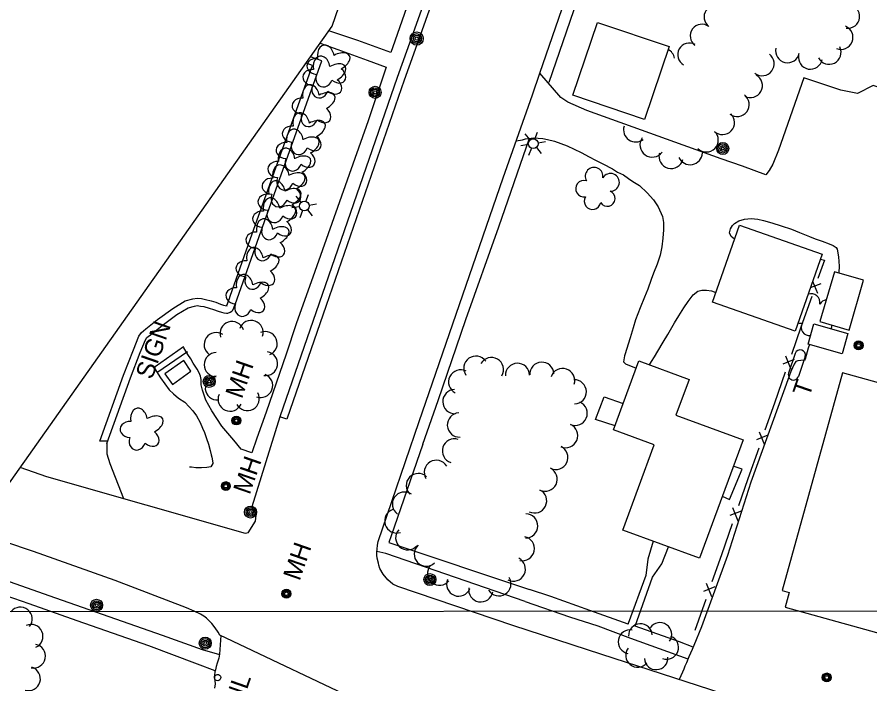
# Model space of a CAD drawing. Extents: x 189384 to 193282, y 256970 to 260388.
# Drawn here: x 190295.2 to 190581.3, y 258486.9 to 258710.5 of the extents above; entities that cross this region are included whole.
import ezdxf

# ---------------------------------------------------------------- set-up
doc = ezdxf.new("R2010")
doc.units = 0
for name, color, linetype in [('E_BLD', 7, 'Continuous'), ('E_BLD_Name', 7, 'Continuous'), ('E_DRN_Grate', 7, 'Continuous'), ('E_DWY', 7, 'Continuous'), ('E_LAND_Vegetation', 7, 'Continuous'), ('E_MAP_GridLines', 7, 'Continuous'), ('E_MAP_Limits', 7, 'Continuous'), ('E_MISCPROP', 7, 'Continuous'), ('E_MISCPROP_HvyDash', 7, 'Continuous'), ('E_MISCPROP_HvyLine', 7, 'Continuous'), ('E_MISCPROP_Railing', 7, 'Continuous'), ('E_PATH_Sidewalk', 7, 'Continuous'), ('E_RDWY', 7, 'Continuous')]:
    doc.layers.add(name, color=color, linetype=linetype)

# ---------------------------------------------------------------- blocks, each defined once
blk = doc.blocks.new('INL')
at = {"layer": 'E_MISCPROP_Railing'}
blk.add_text('INL', height=6, rotation=0, dxfattribs=at).set_placement((-5.79, -2.75))
blk = doc.blocks.new('MHO')
at = {"layer": 'E_DRN_Grate'}
for centre, radius in [((0.04, -0.06), 1.5), ((0.04, -0.06), 1.22), ((0.04, -0.07), 0.968), ((0.01, -0.08), 0.605)]:
    blk.add_circle(centre, radius, dxfattribs=at)
blk = doc.blocks.new('SIGN')
at = {"layer": 'E_MISCPROP'}
blk.add_text('SIGN', height=6, rotation=0, dxfattribs=at).set_placement((0, -3))
blk = doc.blocks.new('LTP')
at = {"layer": 'E_MISCPROP'}
for p, q in [((-0.78, 1.46), (-1.98, 3.76)), ((0.86, 1.37), (2.22, 3.6)), ((-1.61, 0.09), (-4.22, 0.17)), ((1.66, 0), (4.18, -0.06)), ((-0.86, -1.4), (-2.22, -3.59)), ((0.78, -1.44), (2.02, -3.62))]:
    blk.add_line(p, q, dxfattribs=at)
blk.add_circle((0.02, 0.01), 1.64, dxfattribs=at)
blk = doc.blocks.new('POLE')
at = {"layer": 'E_MISCPROP'}
for radius in [2.02, 1.51, 1.01, 0.504]:
    blk.add_circle((0.03, -0.09), radius, dxfattribs=at)
blk = doc.blocks.new('MHO_2')
at = {"layer": 'E_DRN_Grate'}
for centre, radius in [((0.04, -0.06), 1.5), ((0.04, -0.06), 1.22), ((0.04, -0.07), 0.968), ((0.01, -0.08), 0.605)]:
    blk.add_circle(centre, radius, dxfattribs=at)
blk = doc.blocks.new('TREE')
at = {"layer": 'E_LAND_Vegetation'}
for centre, major_axis, ratio in [((-1.07, 3.38), (0.91, -3.32), 0.782863), ((2.88, 1.66), (-3.52, -1.95), 0.691916), ((-3.74, -0.07), (3.29, -0.08), 0.832022), ((-1.48, -3.66), (1.2, 3.24), 0.716896), ((2.54, -2.64), (-3.34, 3.06), 0.560249)]:
    blk.add_ellipse(centre, major_axis=major_axis, ratio=ratio, start_param=1.570796, end_param=4.712389, dxfattribs=at)
blk = doc.blocks.new('MHO_4')
at = {"layer": 'E_DRN_Grate'}
for centre, radius in [((0.04, -0.06), 1.5), ((0.04, -0.06), 1.22), ((0.04, -0.07), 0.968), ((0.01, -0.08), 0.605)]:
    blk.add_circle(centre, radius, dxfattribs=at)
blk = doc.blocks.new('TK5')
at = {"layer": 'E_BLD'}
for p, q in [((1.56, 1.71), (8.66, 1.72)), ((1.66, -1.78), (8.68, -1.78))]:
    blk.add_line(p, q, dxfattribs=at)
for centre, start, end in [((1.67, -0.03), 93.5947, 269.612), ((8.66, -0.03), 270.7756, 93.236)]:
    blk.add_arc(centre, 1.75, start, end, dxfattribs=at)
blk = doc.blocks.new('TA')
at = {"layer": 'E_BLD_Name'}
blk.add_text('T', height=6, rotation=0, dxfattribs=at).set_placement((-1.9, 0.03))
blk = doc.blocks.new('TREE_1')
at = {"layer": 'E_LAND_Vegetation'}
for centre, radius, start, end in [((-1.47, 4.28), 2.78, 1.3946, 209.1676), ((-4.47, 0.2), 2.78, 78.0717, 279.0827), ((3.57, 2.42), 2.97, 278.4237, 139.6576), ((-2.01, -4.2), 2.61, 140.7798, 358.7124), ((3.46, -3.43), 2.97, 196.0746, 79.0478)]:
    blk.add_arc(centre, radius, start, end, dxfattribs=at)
blk = doc.blocks.new('LTP_2')
at = {"layer": 'E_MISCPROP'}
for p, q in [((-0.8, 1.43), (-2, 3.73)), ((0.9, 1.42), (2.27, 3.65)), ((-1.63, 0.07), (-4.24, 0.14)), ((-0.88, -1.42), (-2.24, -3.61)), ((0.76, -1.47), (2, -3.65)), ((1.64, -0.02), (4.16, -0.09))]:
    blk.add_line(p, q, dxfattribs=at)
blk.add_circle((0, 0), 1.64, dxfattribs=at)
blk = doc.blocks.new('POLE_10')
at = {"layer": 'E_MISCPROP'}
for centre, radius in [((-0.01, 0.02), 2.02), ((-0.01, 0.03), 1.52), ((0, -0.01), 1.01), ((0, 0), 0.502)]:
    blk.add_circle(centre, radius, dxfattribs=at)
blk = doc.blocks.new('POLE_12')
at = {"layer": 'E_MISCPROP'}
for centre, radius in [((-0.01, 0.02), 2.22), ((-0.01, 0.03), 1.67), ((0, -0.01), 1.11), ((0, 0), 0.552)]:
    blk.add_circle(centre, radius, dxfattribs=at)
blk = doc.blocks.new('POLE_13')
at = {"layer": 'E_MISCPROP'}
for centre, radius in [((-0.01, 0.02), 2.02), ((-0.01, 0.03), 1.52), ((0, -0.01), 1.01), ((0, 0), 0.502)]:
    blk.add_circle(centre, radius, dxfattribs=at)

msp = doc.modelspace()

# ---------------------------------------------------------------- linework, layer by layer
at = {"layer": 'E_DWY'}
for points in [[(190325.31, 258567.52), (190333.27, 258589.54), (190336.58, 258598.01), (190338.28, 258602.31), (190338.82, 258603.02), (190339.25, 258603.41), (190339.98, 258603.96), (190343.91, 258607.08), (190348.87, 258610.73), (190352.65, 258613.05), (190354.75, 258613.59), (190355.68, 258613.76), (190356.74, 258613.62), (190357.94, 258613.41), (190359.66, 258612.93), (190361.08, 258612.49), (190362.67, 258611.92), (190363.83, 258611.52), (190364.63, 258611.36), (190365.44, 258611.21), (190365.96, 258611.21), (190366.69, 258611.51), (190367.29, 258611.86), (190367.6, 258612.26), (190368, 258612.97), (190368.44, 258614.21), (190368.8, 258615.33), (190369.08, 258616.02), (190376.41, 258636.94), (190397.51, 258695.83), (190393.67, 258697.18)], [(190325.59, 258568.29), (190322.96, 258568.37), (190330.93, 258590.42), (190334.25, 258598.93), (190336.08, 258603.55), (190336.96, 258604.7), (190337.64, 258605.34), (190338.45, 258605.94), (190342.39, 258609.07), (190347.48, 258612.81), (190351.66, 258615.37), (190354.21, 258616.03), (190355.62, 258616.3), (190357.13, 258616.09), (190358.5, 258615.85), (190360.37, 258615.32), (190361.87, 258614.86), (190363.49, 258614.28), (190364.49, 258613.94), (190365.1, 258613.81), (190365.67, 258613.71), (190365.48, 258613.71), (190365.59, 258613.76), (190365.61, 258613.78), (190365.51, 258613.64), (190365.72, 258614.01), (190366.08, 258615.01), (190366.45, 258616.18), (190366.74, 258616.9), (190374.06, 258637.78), (190394.31, 258694.3), (190392.17, 258695.05)], [(190547.55, 258659.02), (190546.39, 258657.59), (190538.6, 258660.48), (190531.4, 258663.02), (190486.38, 258679.22), (190479.97, 258681.95), (190477.61, 258683.5), (190470.58, 258691.68)], [(190596.32, 258675.99), (190588.63, 258680.96), (190590.01, 258684.94), (190582.44, 258687.54), (190577.19, 258684.9), (190571.57, 258686), (190559.14, 258690.11), (190550.63, 258665.86), (190548.76, 258661.15), (190547.55, 258659.02)], [(190462.69, 258668.98), (190464.76, 258669.38), (190465.78, 258669.62), (190466.89, 258669.81), (190468.33, 258670.01), (190470.04, 258669.94), (190471.58, 258669.74), (190473.2, 258669.47), (190475.5, 258668.89), (190477.66, 258668.13), (190479.75, 258667.37), (190482.12, 258666.26), (190484.46, 258665.12), (190487.16, 258663.68), (190489.32, 258662.57), (190491.76, 258661.27), (190495.02, 258659.61), (190496.64, 258658.55), (190498.63, 258657.55), (190500.33, 258656.34), (190501.83, 258655.4), (190503.99, 258654.03), (190506.59, 258651.59), (190508.67, 258649.2), (190510.34, 258646.86), (190511.72, 258643.58), (190512.06, 258641.66), (190512.03, 258639.12), (190511.85, 258636.35), (190511.49, 258633.45), (190510.97, 258630.71), (190509.94, 258627.7), (190508.7, 258624.67), (190507.89, 258622.52), (190506.8, 258619.3), (190505.7, 258616.63), (190504.24, 258612.98), (190502.72, 258609.03), (190501.88, 258606.33), (190500.9, 258602.92), (190500.25, 258600.79), (190499.8, 258599.41), (190499.06, 258597.31), (190498.97, 258596.88), (190498.65, 258594.93), (190499.29, 258594.26), (190502.95, 258592.8)], [(190535.88, 258636), (190534.77, 258636.9), (190534.23, 258638.15), (190534.51, 258639.52), (190535.19, 258640.58), (190535.88, 258641.28), (190537.32, 258642.15), (190539.29, 258642.78), (190541.47, 258642.97), (190543.76, 258642.72), (190545.63, 258642.26), (190548.42, 258641.56), (190551.6, 258640.51), (190555.06, 258639.34), (190557.73, 258638.23), (190561.02, 258636.96), (190562.95, 258636.19), (190565.31, 258635.37), (190567.6, 258634.44), (190568.94, 258633.86), (190569.98, 258633.26), (190570.34, 258632.72), (190570.81, 258630.07), (190570.92, 258628.55), (190570.97, 258626.97), (190570.9, 258624.84), (190570.88, 258624.68)], [(190507.42, 258593.9), (190508.08, 258595), (190509.08, 258596.59), (190510.22, 258598.44), (190512, 258601.45), (190513.57, 258604.04), (190515.77, 258607.96), (190517.25, 258610.38), (190518.9, 258612.99), (190520.37, 258615.13), (190522.07, 258617.36), (190523.64, 258618.55), (190524.97, 258618.98), (190526.52, 258618.99), (190528.21, 258618.72), (190529.66, 258618.17)], [(190561, 258600.75), (190560.59, 258599.47), (190559.93, 258597.09), (190559.57, 258595.81), (190559.32, 258595.42), (190558.11, 258595.34), (190557.17, 258595.3), (190556.51, 258594.98), (190555.92, 258594.12), (190555.35, 258592.95), (190554.81, 258591.7), (190554.22, 258590.12), (190541.33, 258554.62), (190533.55, 258529.98), (190524.78, 258506.1), (190522.22, 258499.76), (190521.67, 258498.44), (190520.63, 258496.05), (190519.74, 258494.04), (190519.25, 258492.84), (190518.85, 258491.92), (190518.43, 258490.9), (190517.32, 258488.43)], [(190325.31, 258567.52), (190325.33, 258564.08), (190326.36, 258560.81), (190330.93, 258549.05)], [(190363.57, 258503.13), (190363.16, 258496.91), (190362.87, 258495.61), (190362.41, 258493.94), (190362.07, 258492.73), (190361.79, 258491.71), (190361.6, 258490.97), (190361.46, 258489.91), (190361.44, 258488.83), (190361.57, 258487.92), (190361.68, 258486.97), (190361.43, 258485.51)]]:
    msp.add_lwpolyline(points, dxfattribs=at)
at = {"layer": 'E_LAND_Vegetation'}
for centre, radius, start, end in [((190529.59, 258710.54), 3.92, 54.3628, 234.3475), ((190573.85, 258710.77), 4.02, 263.041, 83.0257), ((190524.97, 258704.16), 3.92, 53.4828, 233.4674), ((190571.61, 258703.69), 4.02, 247.9529, 67.9375), ((190520.75, 258697.88), 3.92, 60.8018, 240.7865), ((190511.92, 258696.07), 3.92, 10.0714, 64.4041), ((190553.7, 258699.21), 4.02, 167.5427, 347.5274), ((190567.62, 258698.66), 4.02, 206.9125, 26.8972), ((190545.18, 258694.85), 4.02, 232.6906, 52.6752), ((190561.35, 258697.03), 4.02, 169.3399, 349.3246), ((190541.25, 258687.49), 4.02, 241.3693, 61.354), ((190536.79, 258681.18), 4.02, 233.2352, 53.2199), ((190531.89, 258675.11), 4.02, 226.7884, 46.7731), ((190502.78, 258672.75), 4.11, 163.3254, 307.7192), ((190508.29, 258667.64), 4.11, 144.1872, 324.1719), ((190526.43, 258669.28), 4.02, 225.7255, 45.7102), ((190514.65, 258663.82), 4.11, 164.5187, 344.5034), ((190521.02, 258665.1), 4.11, 203.526, 357.6176), ((190561.59, 258614.78), 2.97, 349.2855, 109.7314), ((190567.08, 258612.75), 2.97, 97.8146, 149.9096), ((190367.33, 258604.41), 4.02, 18.5474, 198.532), ((190373.77, 258604.77), 4.02, 341.0533, 161.038), ((190558.18, 258610.62), 2.78, 250.3925, 280.0294), ((190561.05, 258606.45), 2.78, 148.9334, 277.7742), ((190566.01, 258607.34), 2.61, 330.0957, 358.0421), ((190362, 258600.7), 4.02, 55.6486, 235.6333), ((190378.49, 258601.05), 4.02, 293.1, 113.0847), ((190362.05, 258593.97), 4.02, 90.2785, 270.2632), ((190378.6, 258594.32), 4.02, 261.4584, 81.4431), ((190449.12, 258592.78), 4.06, 34.7269, 214.7116), ((190454.35, 258592.31), 4.06, 329.7365, 149.7212), ((190463.11, 258590.37), 4.06, 1.421, 181.4057), ((190471.28, 258590.72), 4.06, 3.0413, 183.026), ((190478.26, 258588.65), 4.06, 341.7283, 161.713), ((190362.39, 258586.14), 4.02, 95.3444, 275.3291), ((190376.97, 258586.95), 4.02, 248.5727, 68.5574), ((190444.04, 258588.18), 4.06, 63.5434, 243.5281), ((190482.14, 258584.85), 4.06, 271.5185, 91.5031), ((190372.49, 258582.58), 4.02, 208.5685, 28.5532), ((190442.1, 258581.58), 4.06, 91.268, 271.2527), ((190366.68, 258582.38), 4.02, 156.4277, 336.4124), ((190482.45, 258577.64), 4.06, 246.9068, 66.8914), ((190443.62, 258573.74), 4.06, 93.152, 273.1366), ((190479.26, 258570.18), 4.06, 246.8365, 66.8212), ((190441.95, 258565.05), 4.06, 72.3476, 252.3323), ((190475.95, 258562.89), 4.06, 244.0249, 64.0096), ((190435.88, 258557.87), 4.06, 31.1576, 211.1423), ((190472.39, 258555.59), 4.06, 244.0249, 64.0096), ((190429.83, 258553.44), 4.06, 46.351, 226.3356), ((190425.19, 258547.21), 4.06, 55.3949, 235.3796), ((190468.84, 258548.29), 4.06, 244.0249, 64.0095), ((190422.61, 258541.57), 4.06, 108.1988, 288.1835), ((190465.84, 258539.93), 4.06, 268.6291, 88.6137), ((190426.29, 258535.92), 4.06, 138.1135, 318.0982), ((190464.7, 258532.29), 4.06, 258.5243, 78.509), ((190432.52, 258530.44), 4.06, 133.2006, 313.1853), ((190461.7, 258525.41), 4.06, 243.3959, 63.3806), ((190436.98, 258524.06), 4.06, 140.7325, 320.7171), ((190443.4, 258520.4), 4.06, 158.0114, 337.9961), ((190456.86, 258520.5), 4.06, 212.135, 32.1197), ((190450.79, 258518.48), 4.06, 169.8779, 349.8625), ((190296.33, 258508.66), 4, 321.5034, 141.4881), ((190299.93, 258502.88), 4, 293.9359, 113.9205), ((190504.33, 258503.16), 3.96, 2.5393, 182.524), ((190510.87, 258503.52), 3.96, 325.662, 145.6467), ((190500.84, 258501.07), 3.96, 79.2066, 259.1913), ((190513.16, 258499.18), 3.96, 249.0836, 69.0683), ((190300.76, 258496.27), 4, 258.9496, 78.9343), ((190503.36, 258496.49), 3.96, 141.2732, 321.2579), ((190509.62, 258495.67), 3.96, 183.6875, 3.6722), ((190299.06, 258488.67), 4, 253.578, 73.5627)]:
    msp.add_arc(centre, radius, start, end, dxfattribs=at)
at = {"layer": 'E_MAP_GridLines'}
for p in [(189647.05, 258510.74), (190147.05, 258511.09), (190147.05, 258511.09)]:
    msp.add_line(p, (191647.04, 258512.16), dxfattribs=at)
at = {"layer": 'E_MAP_Limits'}
for points in [[(190400.94, 258707.45), (190457.96, 258872.88)], [(190173.62, 258386.11), (190400.94, 258707.45)]]:
    msp.add_lwpolyline(points, dxfattribs=at)
at = {"layer": 'E_MISCPROP'}
msp.add_line((190352.45, 258598.27), (190342.09, 258591.18), dxfattribs=at)
at = {"layer": 'E_MISCPROP_HvyDash'}
for points in [[(190495.85, 258573.51), (190489.24, 258575.53), (190492.22, 258583.19)], [(190492.22, 258583.19), (190498.6, 258580.98)], [(190531.81, 258549.9), (190534.27, 258548.79), (190538.43, 258558.91), (190535.49, 258559.91)]]:
    msp.add_lwpolyline(points, dxfattribs=at)
at = {"layer": 'E_MISCPROP_HvyLine'}
for points in [[(190489.9, 258708.67), (190513.94, 258700.59), (190505.73, 258676.18), (190481.69, 258684.27)], [(190537.53, 258640.72), (190565.28, 258631.05), (190556.27, 258605.19), (190528.51, 258614.86)], [(190569.42, 258625.1), (190564.56, 258608.43), (190574.36, 258605.57), (190579.22, 258622.24)], [(190562.54, 258607.65), (190573.96, 258604.43), (190572.04, 258597.64), (190560.63, 258600.86)], [(190538.75, 258568.77), (190524.15, 258529.07), (190498.45, 258538.52), (190508.97, 258567.1), (190495.34, 258572.12), (190503.84, 258595.22), (190520.66, 258589.03), (190516.25, 258577.05)], [(190621.66, 258577.53), (190572.13, 258591.26), (190551.9, 258518.24), (190554.22, 258517.59), (190552.87, 258512.71), (190604.15, 258498.5), (190625.06, 258573.95), (190620.98, 258575.08)]]:
    msp.add_lwpolyline(points, close=True, dxfattribs=at)
at = {"layer": 'E_MISCPROP_Railing'}
for p, q in [((190562.09, 258621.9), (190563.7, 258617.88)), ((190564.83, 258621.11), (190561.32, 258619.69)), ((190555.94, 258595.71), (190552.16, 258594.17)), ((190553.04, 258596.9), (190554.81, 258592.47)), ((190547.05, 258570.3), (190543.27, 258568.77)), ((190544.15, 258571.49), (190545.92, 258567.07)), ((190538.17, 258544.9), (190534.38, 258543.36)), ((190535.27, 258546.09), (190537.03, 258541.66)), ((190529.28, 258519.49), (190525.49, 258517.95)), ((190526.38, 258520.68), (190528.14, 258516.26))]:
    msp.add_line(p, q, dxfattribs=at)
for points in [[(190564.7, 258629.38), (190566.06, 258629.01), (190563.89, 258622.81)], [(190561.79, 258616.8), (190558.18, 258606.48)], [(190558.18, 258606.48), (190555, 258597.4)], [(190552.9, 258591.4), (190549.29, 258581.07)], [(190549.29, 258581.07), (190546.11, 258571.99)], [(190544.01, 258565.99), (190540.4, 258555.67)], [(190540.4, 258555.67), (190537.22, 258546.59)], [(190535.12, 258540.59), (190531.51, 258530.26)], [(190531.51, 258530.26), (190528.33, 258521.18)], [(190526.23, 258515.18), (190522.62, 258504.86)]]:
    msp.add_lwpolyline(points, dxfattribs=at)
msp.add_ellipse((190362.49, 258489.05), major_axis=(-1.02, 0.34), ratio=0.999834, dxfattribs=at)
at = {"layer": 'E_PATH_Sidewalk'}
for points in [[(190447.18, 258841.59), (190468.1, 258834.24), (190461.64, 258816.22), (190441.14, 258757.22), (190436.59, 258744.35), (190421.31, 258700.47)], [(190486.64, 258726.28), (190473.61, 258688.57)], [(190421.31, 258700.47), (190420.65, 258698.62), (190409.57, 258702.6), (190399.86, 258705.93)], [(190396.89, 258701.73), (190402.81, 258699.62), (190412.64, 258696.09), (190419.01, 258693.69), (190413.02, 258675.76), (190403.42, 258648.52), (190395.16, 258625.25), (190388.9, 258607.68), (190385.55, 258597.48), (190378.79, 258578.09), (190375.7, 258569.31), (190373.97, 258564.39), (190370.44, 258565.66), (190367.91, 258568.63), (190363.91, 258573.38), (190360.59, 258578.45), (190358.55, 258582.02), (190357.45, 258585.46), (190357, 258587.16), (190356.95, 258588.95), (190356.81, 258590.12), (190356.34, 258591.24), (190355.66, 258592.41), (190354.35, 258594.48), (190353.52, 258595.97), (190352.55, 258597.35), (190351.2, 258599.61), (190351.04, 258599.97), (190341.59, 258593.26), (190341.42, 258592.96), (190341.41, 258592.55), (190343.39, 258589.51), (190346.24, 258585.51), (190347.71, 258584.14), (190349.36, 258582.76), (190351.48, 258581.39), (190352.96, 258579.85), (190354.2, 258578.49), (190355.42, 258576.85), (190356.67, 258574.58), (190357.49, 258572.65), (190358.12, 258571.24), (190358.8, 258569.21), (190359.43, 258567.29), (190359.99, 258565.16), (190360.33, 258563.78), (190360.54, 258562.9), (190360.79, 258561.75), (190360.89, 258560.97), (190360.92, 258560.82), (190360.25, 258559.67), (190358.91, 258559.46), (190357.14, 258559.37), (190355.25, 258559.41), (190353.8, 258559.56), (190353.07, 258559.62)], [(190431.31, 258567.29), (190436.44, 258581.96), (190445.82, 258609.13), (190456.89, 258640.22), (190467.17, 258669.85)], [(190353.57, 258591.76), (190351.23, 258595.32), (190344.85, 258590.9), (190347.42, 258587.33)], [(190347.42, 258587.33), (190353.58, 258591.77)], [(190431.31, 258567.29), (190420.76, 258536.6), (190419.97, 258534.35), (190467.09, 258518.54)], [(190508.65, 258534.77), (190506.8, 258528.79), (190506.18, 258523.32), (190500.28, 258507.17), (190500.23, 258506.94), (190487.36, 258511.55), (190474.26, 258516.24), (190467.09, 258518.54)], [(190522.02, 258499.28), (190517.5, 258501.03), (190502.57, 258506.31), (190508.34, 258522.72), (190511.49, 258527.21), (190513.7, 258532.91)], [(190465.72, 258514.62), (190418.99, 258530.66), (190415.95, 258531.37)], [(190273.86, 258527.82), (190305.9, 258516.55), (190343.88, 258503.28), (190357.37, 258498.47), (190363.15, 258496.85)], [(190361.69, 258491.32), (190355.73, 258493.6), (190339.4, 258499.68), (190315.41, 258508.06), (190299.27, 258513.79), (190270.93, 258523.67)], [(190465.72, 258514.62), (190480.57, 258509.45), (190490.07, 258506.4), (190501.03, 258502.22), (190520.29, 258495.29)]]:
    msp.add_lwpolyline(points, dxfattribs=at)
at = {"layer": 'E_RDWY'}
for points in [[(190470.58, 258691.68), (190483.37, 258728.62), (190493.78, 258758.71), (190502.09, 258782.76), (190516.78, 258824.81), (190517.11, 258825.92)], [(190441.39, 258742.52), (190425.87, 258698.91), (190422.78, 258690.21), (190396.55, 258614.58), (190383.33, 258576.48)], [(190443.77, 258741.74), (190428.24, 258698.1), (190425.13, 258689.38), (190398.92, 258613.76), (190385.7, 258575.66), (190383.33, 258576.48)], [(190531.81, 258483.75), (190491.4, 258496.8), (190461.58, 258506.56), (190423, 258519.58), (190421.32, 258520.36), (190419.57, 258521.86), (190418.04, 258523.69), (190416.98, 258525.61), (190416.57, 258526.7), (190416.43, 258527.38), (190416.05, 258529.08), (190415.95, 258530.1), (190415.92, 258530.98), (190416.04, 258532.26), (190416.19, 258533.35), (190416.29, 258534.1), (190416.37, 258534.63), (190430.1, 258574.91), (190458.29, 258656.54), (190468.17, 258684.43), (190470.58, 258691.68)], [(190383.43, 258576.45), (190374.01, 258546.29), (190374.67, 258545.12), (190375.04, 258544.36), (190375.28, 258543.51), (190375.26, 258542.51), (190375.1, 258541.48), (190372.66, 258537.63), (190371.9, 258537.41), (190305.19, 258556.37), (190296.26, 258559.47)], [(190413.73, 258479.4), (190363.26, 258503.28), (190362.68, 258504.3), (190361.72, 258505.76), (190360.54, 258507.17), (190359.5, 258508.32), (190358.8, 258508.93), (190357.94, 258509.61), (190356.78, 258510.34), (190354.68, 258511.37), (190352.1, 258512.44), (190328.17, 258521.64), (190300.8, 258531.34), (190281.02, 258537.93)]]:
    msp.add_lwpolyline(points, dxfattribs=at)

# ---------------------------------------------------------------- block references
at = {"layer": 'E_BLD', "rotation": -108.80157679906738}
msp.add_blockref('TK5', (190558.49, 258598.74), dxfattribs=at)
at = {"layer": 'E_BLD_Name', "rotation": 70.86176541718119}
msp.add_blockref('TA', (190561.58, 258584.64), dxfattribs=at)
at = {"layer": 'E_DRN_Grate'}
for name, p, rotation in [('MHO_4', (190577.44, 258600.4), 70.86176513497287), ('MHO_2', (190368.72, 258575.22), 70.86176885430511), ('MHO', (190365.26, 258553.31), -19.225564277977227), ('MHO', (190385.57, 258517.25), -19.22556464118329), ('MHO_4', (190566.77, 258489.08), 70.8617653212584)]:
    msp.add_blockref(name, p, dxfattribs=dict(at, rotation=rotation))
at = {"layer": 'E_LAND_Vegetation'}
for name, p, rotation in [('TREE', (190399.44, 258693.86), 70.86176831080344), ('TREE', (190398.07, 258690.16), 70.861768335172), ('TREE', (190394.46, 258680.56), 70.861768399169), ('TREE', (190391.17, 258671.17), 70.86176845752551), ('TREE', (190389.11, 258665.64), 70.86176849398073), ('TREE', (190386.33, 258659.27), 70.8617685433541), ('TREE', (190384.39, 258653.67), 70.86176857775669), ('TREE_1', (190489.92, 258652.93), 70.86176669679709), ('TREE', (190383.03, 258648.35), 70.86176860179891), ('TREE', (190381.23, 258642.63), 70.8617686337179), ('TREE', (190378.97, 258635.58), 70.86176867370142), ('TREE', (190375.65, 258626.02), 70.861768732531), ('TREE', (190372.24, 258616.94), 70.86176879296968), ('TREE', (190336.79, 258572.12), 70.8617694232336)]:
    msp.add_blockref(name, p, dxfattribs=dict(at, rotation=rotation))
at = {"layer": 'E_MISCPROP'}
for name, p, rotation in [('POLE_12', (190429.31, 258703.27), 71.03735472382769), ('POLE', (190415.24, 258685.26), 70.86176802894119), ('LTP_2', (190468.37, 258668.04), 70.86176708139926), ('POLE_13', (190531.98, 258666.44), 71.03735289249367), ('LTP', (190391.58, 258647.13), 70.86176844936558), ('SIGN', (190337.68, 258589.69), 70.86176940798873), ('POLE', (190359.6, 258588.34), 70.86176901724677), ('POLE', (190373.46, 258544.56), 70.86176876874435), ('POLE', (190433.63, 258521.92), 70.8617676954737)]:
    msp.add_blockref(name, p, dxfattribs=dict(at, rotation=rotation))
at = {"layer": 'E_MISCPROP', "yscale": 1.0000015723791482}
for p, xscale, rotation in [((190321.93, 258513.32), 1.0000015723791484, 71.7402614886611), ((190358.38, 258500.6), 1.0000015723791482, 71.74026083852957)]:
    msp.add_blockref('POLE_10', p, dxfattribs=dict(at, xscale=xscale, rotation=rotation))
at = {"layer": 'E_MISCPROP_Railing', "rotation": 70.77443565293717}
msp.add_blockref('INL', (190369, 258483.61), dxfattribs=at)

# ---------------------------------------------------------------- texts
at = {"layer": 'E_DRN_Grate'}
for rotation, p in [(70.8619, (190370.63, 258582.28)), (70.8619, (190373.25, 258550.12)), (70.7744, (190389.99, 258521.23))]:
    msp.add_text('MH', height=6, rotation=rotation, dxfattribs=at).set_placement(p)

doc.saveas('drawing.dxf')
